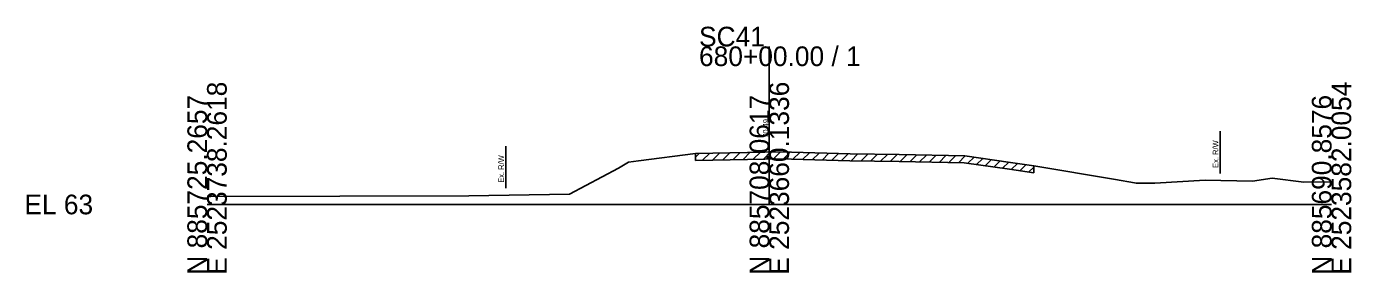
# Model space of a CAD drawing. Extents: x -26 to 183, y -10 to 24021.
# Drawn here: x -25.7 to 162.8, y 11990.3 to 12025.4 of the extents above; entities that cross this region are included whole.
import ezdxf

# ---------------------------------------------------------------- set-up
doc = ezdxf.new("R2010")
doc.units = 0
for name, color, linetype in [('RD_GPK_XS_Cell', 7, 'Continuous'), ('RD_XS_ExGround', 7, 'Continuous'), ('RD_XS_ExPaveRet', 7, 'Continuous'), ('RD_XS_ExRW', 7, 'Continuous'), ('RD_XS_TX_Elev_EX', 7, 'Continuous')]:
    doc.layers.add(name, color=color, linetype=linetype)

msp = doc.modelspace()

# ---------------------------------------------------------------- linework, layer by layer
at = {"layer": 'RD_GPK_XS_Cell'}
for p, q in [((80, 12000), (80, 12022.51)), ((0, 12000), (80, 12000)), ((80, 12000), (160, 12000))]:
    msp.add_line(p, q, dxfattribs=at)
at = {"layer": 'RD_XS_ExGround'}
for p, q in [((58.52, 12005.19), (59.96, 12006.03)), ((59.96, 12006.03), (61.39, 12006.22)), ((61.39, 12006.22), (69.52, 12007.28)), ((69.52, 12007.28), (79.35, 12007.47)), ((79.35, 12007.47), (80, 12007.49)), ((80, 12007.49), (80.88, 12007.5)), ((80.88, 12007.5), (83.17, 12007.44)), ((83.17, 12007.44), (91.49, 12007.22)), ((91.49, 12007.22), (98.49, 12007.11)), ((98.49, 12007.11), (107.8, 12006.93)), ((107.8, 12006.93), (114.32, 12006)), ((114.32, 12006), (117.62, 12005.52)), ((51.55, 12001.45), (58.52, 12005.19)), ((117.62, 12005.52), (129.25, 12003.56)), ((129.25, 12003.56), (131.97, 12003.1)), ((131.97, 12003.1), (132.22, 12003.04)), ((132.22, 12003.04), (134.87, 12003.02)), ((134.87, 12003.02), (142.04, 12003.47)), ((142.04, 12003.47), (148.75, 12003.32)), ((148.75, 12003.32), (151.57, 12003.77)), ((151.57, 12003.77), (156.08, 12003.19)), ((156.08, 12003.19), (160, 12003.22)), ((0, 12001.13), (0.55, 12001.13)), ((0.55, 12001.13), (37.26, 12001.22)), ((37.26, 12001.22), (51.55, 12001.45))]:
    msp.add_line(p, q, dxfattribs=at)
at = {"layer": 'RD_XS_ExPaveRet'}
for p, q in [((69.52, 12006.73), (70.08, 12007.29)), ((69.52, 12006.28), (79.37, 12006.47)), ((70.5, 12006.3), (71.52, 12007.32)), ((71.94, 12006.33), (72.97, 12007.35)), ((73.39, 12006.35), (74.41, 12007.38)), ((74.83, 12006.38), (75.85, 12007.4)), ((76.27, 12006.41), (77.29, 12007.43)), ((77.72, 12006.44), (78.74, 12007.46)), ((79.16, 12006.47), (80.18, 12007.49)), ((79.37, 12006.47), (80, 12006.49)), ((80, 12006.49), (80.88, 12006.5)), ((80.6, 12006.5), (81.59, 12007.48)), ((80.88, 12006.5), (83.15, 12006.44)), ((81.99, 12006.47), (82.96, 12007.44)), ((83.15, 12006.44), (91.47, 12006.22)), ((83.37, 12006.43), (84.34, 12007.41)), ((84.74, 12006.4), (85.72, 12007.37)), ((86.12, 12006.36), (87.09, 12007.33)), ((87.5, 12006.32), (88.47, 12007.3)), ((88.88, 12006.29), (89.85, 12007.26)), ((90.25, 12006.25), (91.23, 12007.22)), ((91.47, 12006.22), (98.47, 12006.11)), ((91.63, 12006.22), (92.62, 12007.2)), ((93.03, 12006.19), (94.01, 12007.18)), ((94.42, 12006.17), (95.4, 12007.16)), ((95.81, 12006.15), (96.8, 12007.14)), ((97.2, 12006.13), (98.19, 12007.11)), ((98.47, 12006.11), (107.72, 12005.93)), ((98.6, 12006.11), (99.58, 12007.09)), ((99.98, 12006.08), (100.97, 12007.06)), ((101.37, 12006.06), (102.35, 12007.04)), ((102.76, 12006.03), (103.74, 12007.01)), ((104.15, 12006), (105.13, 12006.98)), ((105.54, 12005.98), (106.52, 12006.96)), ((106.92, 12005.95), (107.89, 12006.92)), ((107.72, 12005.93), (114.18, 12005.01)), ((108.25, 12005.86), (109.13, 12006.74)), ((109.48, 12005.68), (110.37, 12006.57)), ((110.72, 12005.51), (111.61, 12006.39)), ((111.96, 12005.33), (112.84, 12006.21)), ((113.2, 12005.15), (114.08, 12006.04)), ((114.43, 12004.97), (115.31, 12005.85)), ((114.18, 12005.01), (117.62, 12004.5)), ((115.67, 12004.79), (116.55, 12005.67)), ((116.9, 12004.61), (117.62, 12005.33))]:
    msp.add_line(p, q, dxfattribs=at)
for points in [[(69.52, 12007.28), (69.52, 12006.28)], [(117.62, 12005.52), (117.62, 12005.52)], [(117.62, 12005.52), (117.62, 12004.5)]]:
    msp.add_lwpolyline(points, dxfattribs=at)
at = {"layer": 'RD_XS_ExRW'}
for p, q in [((144.15, 12010.42), (144.15, 12004.42)), ((42.5, 12008.31), (42.5, 12002.31))]:
    msp.add_line(p, q, dxfattribs=at)

# ---------------------------------------------------------------- texts
at = {"layer": 'RD_GPK_XS_Cell'}
for s, p in [('SC41', (70, 12022.51)), ('680+00.00 / 1', (70, 12019.71)), ('EL 63', (-26, 11998.6))]:
    msp.add_text(s, height=2.8, dxfattribs=at).set_placement(p)
for s, p in [('E 2523738.2618', (2.8, 11990)), ('E 2523660.1336', (82.8, 11990)), ('E 2523582.0054', (162.8, 11990)), ('N 885725.2657', (0, 11990)), ('N 885708.0617', (80, 11990)), ('N 885690.8576', (160, 11990))]:
    msp.add_text(s, height=2.8, rotation=90, dxfattribs=at).set_placement(p)
at = {"layer": 'RD_XS_ExRW'}
for p in [(143.9, 12005.21), (42.25, 12003.09)]:
    msp.add_text('Ex. R/W ', height=0.8, rotation=90, dxfattribs=at).set_placement(p)
at = {"layer": 'RD_XS_TX_Elev_EX'}
msp.add_text('70.49', height=0.8, rotation=90, dxfattribs=at).set_placement((79.9, 12009.49))

doc.saveas('drawing.dxf')
